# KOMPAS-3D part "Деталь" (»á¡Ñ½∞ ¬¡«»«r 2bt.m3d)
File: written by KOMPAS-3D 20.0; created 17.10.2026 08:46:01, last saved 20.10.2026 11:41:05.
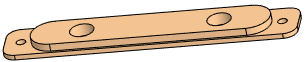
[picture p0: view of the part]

Document properties: Полное имя файла: D:\RicWork\Project-EPS32\box_compas\корпус\панель кнопоr v2.m3d

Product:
- Part/product: Деталь
    Масса: 0.0319261

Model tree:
1. Эскиз:1
2. Элемент выдавливания:1
     Расстояние 1 = 1.6
3. Эскиз:5  (with: Элемент выдавливания:1)
4. Элемент выдавливания:6
     Расстояние 2 = 1.6
5. Эскиз:6  (with: Элемент выдавливания:1, Элемент выдавливания:6)
6. Элемент выдавливания:7
     Расстояние 1 = 2.4
7. Эскиз:7  (with: Элемент выдавливания:7, Элемент выдавливания:1)
8. Элемент выдавливания:8
     Расстояние 2 = 4
9. Массив по сетке:1  (with: Элемент выдавливания:8, Эскиз:7)  (2 pattern instances)
     Шаг 1 = 42; Угол раствора = 90
10. Элемент выдавливания:9  (with: Элемент выдавливания:1)
     Расстояние 1 = 2
11. Элемент выдавливания:10  (with: Элемент выдавливания:1)
     Расстояние 1 = 2
12. Элемент выдавливания:11  (with: Элемент выдавливания:1)
     Расстояние 2 = 0.25
13. Элемент выдавливания:12  (with: Элемент выдавливания:1)
     Расстояние 2 = 0.25
14. Скругление:5  (with: Элемент выдавливания:1, Скругление:4, Элемент выдавливания:11, Элемент выдавливания:9, Скругление:3, Элемент выдавливания:12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)
     Радиус = 0.6
15. Элемент выдавливания:13  (with: Элемент выдавливания:12)
     Расстояние 2 = 0.2
16. Элемент выдавливания:14  (with: Элемент выдавливания:11)
     Расстояние 2 = 0.2
17. Скругление:6  (with: Элемент выдавливания:14, Элемент выдавливания:13)
     Радиус = 4
18. Эскиз:8  (with: Элемент выдавливания:1, Элемент выдавливания:6, Элемент выдавливания:8, Элемент выдавливания:9, Элемент выдавливания:10, Элемент выдавливания:13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)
